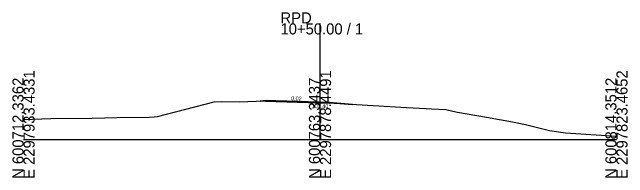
# Model space of a CAD drawing. Extents: x -313 to 385, y -480 to 1023.
# Drawn here: x -2.8 to 152.8, y -9.7 to 32.2 of the extents above; entities that cross this region are included whole.
import ezdxf

# ---------------------------------------------------------------- set-up
doc = ezdxf.new("R2010")
doc.units = 0
for name, color, linetype in [('Exist Cross Section Cell', 7, 'Continuous'), ('Exist XS Center Line Elevation Label', 7, 'Continuous'), ('Exist XS Ground Line', 7, 'Continuous'), ('Prop CMT Pvmt Surface', 7, 'Continuous'), ('Prop CMT Pvmt Surface Overlay', 7, 'Continuous'), ('Prop CMT Slope Grass', 7, 'Continuous'), ('Prop XS Earthwork Shape', 7, 'Continuous'), ('Prop XS SE Text', 7, 'Continuous')]:
    doc.layers.add(name, color=color, linetype=linetype)

msp = doc.modelspace()

# ---------------------------------------------------------------- linework, layer by layer
at = {"layer": 'Exist Cross Section Cell'}
for p, q in [((75, 0), (75, 29.36)), ((0, 0), (75, 0)), ((75, 0), (150, 0))]:
    msp.add_line(p, q, dxfattribs=at)
at = {"layer": 'Exist XS Ground Line'}
msp.add_lwpolyline([(0, 5.01), (6.88, 5.25), (17.37, 5.38), (23.59, 5.51), (31.81, 5.64), (33.05, 5.67), (33.85, 5.83), (48.19, 9.48), (50.2, 9.55), (54.52, 9.5), (61.01, 9.74), (61.46, 9.76), (61.84, 9.79), (62.73, 9.77), (64.46, 9.71), (66.06, 9.66), (66.41, 9.65), (68, 9.6), (69.47, 9.56), (70.08, 9.54), (72.88, 9.46), (73.31, 9.45), (73.76, 9.44), (75.26, 9.39), (76.13, 9.4), (77.09, 9.24), (80.02, 9.05), (96.88, 8.1), (101.85, 7.79), (103.24, 7.74), (106.85, 7.55), (108.58, 7.15), (109.82, 6.91), (117.14, 5.66), (123.74, 4.47), (125.72, 4.03), (127, 3.81), (133.05, 2.29), (137.13, 1.7), (150, 0.82)], dxfattribs=at)
at = {"layer": 'Prop CMT Pvmt Surface'}
for p, q in [((77.42, 9.34), (61.23, 9.81)), ((61.23, 9.56), (61.23, 9.81)), ((77.42, 9.09), (61.23, 9.56)), ((77.42, 9.34), (77.42, 9.09))]:
    msp.add_line(p, q, dxfattribs=at)
at = {"layer": 'Prop CMT Pvmt Surface Overlay'}
for p, q in [((77.42, 9.34), (61.23, 9.81)), ((61.23, 9.56), (61.23, 9.81)), ((77.42, 9.09), (61.23, 9.56)), ((77.42, 9.34), (77.42, 9.09))]:
    msp.add_line(p, q, dxfattribs=at)
at = {"layer": 'Prop CMT Slope Grass'}
for p, q in [((61.23, 9.81), (59.88, 9.7)), ((61.23, 9.81), (61.23, 9.75)), ((77.42, 9.34), (83.21, 8.87)), ((77.42, 9.34), (77.42, 9.22))]:
    msp.add_line(p, q, dxfattribs=at)
at = {"layer": 'Prop XS Earthwork Shape'}
for points in [[(61.23, 9.81), (61.23, 9.75), (61.01, 9.74), (59.88, 9.7)], [(77.42, 9.22), (80.02, 9.05), (83.21, 8.87), (77.42, 9.34)]]:
    msp.add_lwpolyline(points, close=True, dxfattribs=at)

# ---------------------------------------------------------------- texts
at = {"layer": 'Exist Cross Section Cell'}
for s, p in [('RPD', (65, 29.36)), ('10+50.00 / 1', (65, 26.56))]:
    msp.add_text(s, height=2.8, dxfattribs=at).set_placement(p)
for s, p in [('E 2297933.4331', (2.8, -10)), ('E 2297878.4491', (77.8, -10)), ('E 2297823.4652', (152.8, -10)), ('N 600712.3362', (0, -10)), ('N 600763.3437', (75, -10)), ('N 600814.3512', (150, -10))]:
    msp.add_text(s, height=2.8, rotation=90, dxfattribs=at).set_placement(p)
at = {"layer": 'Exist XS Center Line Elevation Label'}
msp.add_text('103.40', height=1, dxfattribs=at).set_placement((72.88, 7.9))
at = {"layer": 'Prop XS SE Text'}
msp.add_text('0.02', height=1, rotation=357.1594, dxfattribs=at).set_placement((67.65, 9.93))

doc.saveas('drawing.dxf')
